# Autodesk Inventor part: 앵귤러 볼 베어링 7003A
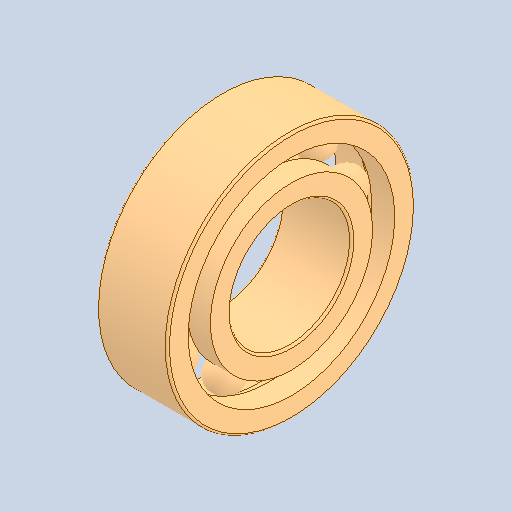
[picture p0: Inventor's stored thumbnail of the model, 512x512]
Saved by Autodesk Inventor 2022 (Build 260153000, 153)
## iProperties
Created: 2024-11
Part Number: 앵귤러 볼 베어링 7003A
Material: 강철, 연강
Description: 앵귤러 콘택트 볼 베어링
Document SubType Name: Modeling
Designer: PC-12
Density: 7.85 g/cm^3
Appearance: 기본값
Author: jhkim
Sending System: Autodesk Inventor 2025
Preprocessor: ST-DEVELOPER v20
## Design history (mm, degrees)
node "앵귤러 볼 베어링 7003A1"
node "솔리드1"
node "솔리드2"
node "솔리드3"
node "솔리드4"
node "솔리드5"
node "솔리드6"
node "솔리드7"
node "솔리드8"
node "솔리드9"
node "솔리드10"
node "솔리드11"
body "Solid1"
node "Solid1:1"
node "Solid1:2"
node "Solid1:3"
node "Solid1:4"
node "Solid1:5"
node "Solid1:6"
node "Solid1:7"
node "Solid1:8"
node "Solid1:9"
node "Solid1:10"
